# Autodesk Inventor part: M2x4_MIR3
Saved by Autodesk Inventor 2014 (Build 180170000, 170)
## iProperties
Created: 2015-05
Part Number: M2x4_MIR3
Material: 일반
Vendor: CBT Solutions
Document SubType Name: 모델링
Designer: Administrator
Appearance: 기본값
Company: 한국ATC센터
Author: KYOUNG IL JANG
Comments: 파생
d0: 1.000 ul
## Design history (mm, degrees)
derived "M2x4.ipt" dims count "d0" = 1
feature "솔리드1::M2x4.ipt" dims count "d0" = 1
tag "피쳐 태그1"
node "솔리드1"
